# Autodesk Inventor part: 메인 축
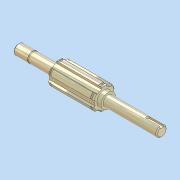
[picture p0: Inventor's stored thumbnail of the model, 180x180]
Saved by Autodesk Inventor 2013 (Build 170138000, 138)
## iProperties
Company: 한국ATC센터
Created: 2014-07
Part Number: 메인 축
Document SubType Name: 모델링
Designer: KYOUNG IL JANG
Mass: 21.4461 g
Surface Area: 72.5104 cm^2
Volume: 21.4461 cm^3
Density: 1 g/cm^3
Material: 일반
변환 표준: STEP AP214IS
파일 이름: C:\Users\SeoGD\Desktop\?쒗뿕\硫붿씤 異?.stp
전처리기: Build: 253, Release: 2010 SP1 - Date: Wed 07/29/2009
전송 단위: 밀리미터
불확실성: 0.01
Author: KYOUNG IL JANG
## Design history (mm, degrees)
sketch "스케치1"
  geometry: L1 (-69.5, 0)-(69.5, 0); L2 (69.5, 0)-(69.5, 5); L3 (69.5, 5)-(55.5, 5); L4 (55.5, 5)-(55.5, 4.8); L5 (55.5, 4.8)-(54.35, 4.8); L6 (54.35, 4.8)-(54.35, 5); L7 (54.35, 5)-(30.5, 5); L8 (30.5, 5)-(30.5, 9); L9 (30.5, 9)-(-13.5, 9); L10 (-13.5, 9)-(-13.5, 7); L11 (-13.5, 7)-(-17.5, 7); L12 (-17.5, 7)-(-17.5, 5); L13 (-17.5, 5)-(-69.5, 5); L14 (-69.5, 5)-(-69.5, 0); 2 further points
  constraints: 28 end point, 9 parallel, 4 collinear, 2 perpendicular, 1 coincident, 1 horizontal, 1 midpoint
  dimensions: "d2" = 1.15 distance between parallel lines of L6 L4; "d3" = 10 diameter of L3 L1; "d4" = 9.6 diameter of L5 L1; "d6" = 44 distance between parallel lines of L10 L8; "d7" = 4 distance between parallel lines of L12 L10; "d8" = 14 diameter of L11 L1; "d9" = 18 diameter of L9 L1; "d33" = 52 distance from line of L12.end L14; "d37" = 39 distance between parallel lines of L8 L2; "d38" = 14 distance between parallel lines of L2 L4
revolve "회전1" sketch "스케치1" stored, may be unused: angle "d10" = 90 deg
sketch "스케치2"
  geometry: L1 (2.5, 10.712)-(2.5, 8.646); L2 (-2.5, 10.712)-(-2.5, 8.646); A1 r 9 centre (0, 0) between (2.5, 8.646) and (-2.5, 8.646) reference; A2 r 11 centre (0, 0) between (2.5, 10.712) and (-2.5, 10.712); 1 further point
  constraints: 4 end point, 4 point on circle, 2 parallel, 1 centre point, 1 coincident, 1 vertical
  dimensions: "d11" = 22 diameter of A2; "d12" = 5 distance between parallel lines of L1 L2
extrude "돌출1" join sketch "스케치2" stored distance "d13" = 10; taper "d14" = 0 deg
chamfer "모따기1" distance "d15" = 1; stored, may be unused: second distance "d16" = 2, angle "d17" = 45 deg
node "작업 평면1"
node "작업 평면2"
sketch "스케치3"
  geometry: L1 (2.5, 10.712)-(2.5, 10.198); L2 (-2.5, 10.712)-(-2.5, 10.198); A1 r 11 centre (0, 0) between (2.5, 10.712) and (-2.5, 10.712) reference; A2 r 10.5 centre (0, 0) between (2.5, 10.198) and (-2.5, 10.198); 1 further point
  constraints: 4 end point, 2 point on circle, 1 centre point, 1 coincident, 1 parallel, 1 vertical
  dimensions: "d19" = 21 diameter of A2
extrude "돌출2" cut sketch "스케치3" distance "d20" = 1.35; taper "d21" = 0 deg
node "작업 평면3"
sketch "스케치4"
  geometry: L1 (-26, -5)-(-26, 5) reference; L2 (-26, 1.5)-(-12.5, 1.5); L3 (-12.5, -1.5)-(-26, -1.5); A1 r 1.5 centre (-12.5, 0) between (-12.5, -1.5) and (-12.5, 1.5); 2 further points
  constraints: 4 end point, 2 perpendicular, 2 point on circle, 2 point on line, 2 tangent, 1 centre point, 1 horizontal alignment, 1 midpoint
  dimensions: "d25" = 3 distance between parallel lines of L3 L2; "d26" = 15 dimension on A1 L1
extrude "돌출3" cut sketch "스케치4" distance "d27" = 1.8; taper "d28" = 0 deg
chamfer "모따기2" distance "d29" = 1; stored, may be unused: second distance "d30" = 2, angle "d31" = 45 deg
node "솔리드1"
node "솔리드 본체"
node "곡면 본체"
mirror "대칭1"
pattern_circular "원형 패턴1" dims "d23" = 360 deg
node "솔리드2"
other parameters: "d18" = -1.65
